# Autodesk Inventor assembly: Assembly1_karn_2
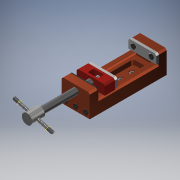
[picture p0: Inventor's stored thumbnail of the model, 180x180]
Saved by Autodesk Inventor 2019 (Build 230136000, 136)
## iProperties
Created: 2018-11
Part Number: Assembly1_karn_2
Document SubType Name: Assembly
Designer: Synergysoft
Author: Synergysoft
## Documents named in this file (9)
- C:\Users\Synergysoft\Desktop\INV-01 for Trainning\Vise\Assembly1_karn_2.iam
- C:\Users\Synergysoft\Desktop\INV-01 for Trainning\Vise\Body.ipt
- C:\Users\Synergysoft\Desktop\INV-01 for Trainning\Vise\FixedJaw.ipt
- C:\Users\Synergysoft\Desktop\INV-01 for Trainning\Vise\MovingJaw.ipt
- C:\Users\Synergysoft\Desktop\INV-01 for Trainning\Vise\Pin.ipt
- C:\Users\Synergysoft\Desktop\INV-01 for Trainning\Vise\Spindle.ipt
- C:\Users\Synergysoft\Documents\Inventor\Content Center Files\R2019\en-US\ISO 10642(1)\ISO 10642 - M5 x  8.ipt
- C:\Users\Synergysoft\Documents\Inventor\Content Center Files\R2019\en-US\ISO 4762(2)\ISO 4762 - M5 x 10ISO.ipt
- C:\Users\Synergysoft\Desktop\INV-01 for Trainning\Vise\Seal.ipt
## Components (21 placed, 8 different names)
1. Body:1 — Insert:1, Insert:2, Mate:1, Flush:1, Mate:5, Mate:19, Mate:21, Mate:23, Mate:25, Flush:2, Flush:3
2. FixedJaw:1 — Insert:1, Insert:2, Moving
3. MovingJaw:1 — Insert:3, Insert:4, Mate:1, Flush:1, Mate:6, Rotation/Translation:1
4. Pin:1 — Mate:3, Mate:4
5. Spindle:1 — Mate:3, Mate:4, Mate:5, Mate:6, Rotation/Translation:1
6. FixedJaw:2 — Insert:3, Insert:4, Moving
7. ISO 10642 M5 x  8:1
8. ISO 10642 M5 x  8:2
9. ISO 10642 M5 x  8:3
10. ISO 10642 M5 x  8:4
11. ISO 10642 M5 x  8:5
12. ISO 10642 M5 x  8:6
13. ISO 10642 M5 x  8:7
14. ISO 10642 M5 x  8:8
15. ISO 10642 M5 x  8:9
16. ISO 10642 M5 x  8:10
17. ISO 4762 M5 x 10:1 — Mate:19
18. ISO 4762 M5 x 10:2 — Mate:21
19. ISO 4762 M5 x 10:3 — Mate:23
20. ISO 4762 M5 x 10:4 — Mate:25
21. Seal:1 — Flush:2, Flush:3
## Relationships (18: Mate 10, Insert 4, Flush 3, RelateRotateTranslate 1)
- Insert:1: Body:1 ↔ FixedJaw:1
- Insert:2: Body:1 ↔ FixedJaw:1
- Insert:3: MovingJaw:1 ↔ FixedJaw:2
- Insert:4: MovingJaw:1 ↔ FixedJaw:2
- Mate:1: Body:1 ↔ MovingJaw:1
- Flush:1: Body:1 ↔ MovingJaw:1
- Mate:3: Pin:1 ↔ Spindle:1
- Mate:4: Pin:1 ↔ Spindle:1
- Mate:5: Body:1 ↔ Spindle:1
- Mate:6: MovingJaw:1 ↔ Spindle:1
- Moving [Mate]: FixedJaw:1 ↔ FixedJaw:2
- Mate:19: Body:1 ↔ ISO 4762 M5 x 10:1
- Mate:21: Body:1 ↔ ISO 4762 M5 x 10:2
- Mate:23: Body:1 ↔ ISO 4762 M5 x 10:3
- Mate:25: Body:1 ↔ ISO 4762 M5 x 10:4
- Rotation/Translation:1 [RelateRotateTranslate]: MovingJaw:1 ↔ Spindle:1
- Flush:2: Body:1 ↔ Seal:1
- Flush:3: Body:1 ↔ Seal:1
